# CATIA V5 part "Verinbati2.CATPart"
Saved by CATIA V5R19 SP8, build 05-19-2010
Part number: Vérin bati
Bounding box of the stored display mesh (mm): x -45 to 45, y -60 to 190, z -45 to 45
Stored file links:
  C:\Users\ThinkMotion\Desktop\EU_thinkMotion\iao\IAO_MMS_Groupe3\yschmidt\Train1434_yschmidt\Train1434_yschmidt\Verinbati2.CATPart
  C:\Users\ThinkMotion\Desktop\EU_thinkMotion\iao\IAO_MMS_Groupe3\yschmidt\Train1434_yschmidt\Train1434_yschmidt\AssemblageTrainOptimise.CATProduct
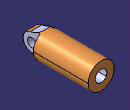
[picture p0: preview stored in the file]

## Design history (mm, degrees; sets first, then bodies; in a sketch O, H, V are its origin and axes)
Set1
  Plane1: linked copy from another document
  Line1: linked copy from another document
Body1 (main body)
  Sketch1 on zx-plane, origin (0, 0, 0), H (-1, 0, 0), V (0, 0, 1)
    circle A1 centre (0, 0) radius 45
    radius A1 = 45
  Pad1: profile Sketch1, direction (0, 1, 0), up to Plane1
  SolidCombine1: FirstComponentProfile Sketch5, FirstComponentDirection Sketch5, SecondComponentProfile Sketch4, SecondComponentDirection Sketch4
  Sketch2 on face of SolidCombine1 from Sketch4.L1, origin (20, -42.0705, -0.8635), H (0, 1, 0), V (0, 0, 1)
    point P1 (12.0705, 0.8635)
    reference projected point E1 (12.0705, 0.8635) from Line1
    coincidence: E1 P1
  Hole1: placed by Sketch2, at (20, -30, 0) direction (-1, 0, 0), diameter 30, through (limit type 6)
  Sketch3 on end face of Pad1, origin (0, 190, 0), H (1, 0, 0), V (0, 0, -1)
    point P1 (0, 0)
  Hole2: placed by Sketch3, at (0, 190, 0) direction (0, -1, 0), diameter 40, depth 180
  Sketch4 on start face of Pad1, origin (0, 0, 0), H (1, 0, 0), V (0, 0, 1)
    arc A1 centre (0, 0) radius 45 from (20, 40.3113) to (-20, 40.3113) ccw
    point P1 (0, 45)
    line L1 (20, 40.3113) -> (20, -40.3113)
    line L2 (-20, 40.3113) -> (-20, -40.3113)
    point P5 (-20, -40.3113)
    arc A2 centre (0, 0) radius 45 from (-20, -40.3113) to (20, -40.3113) ccw
    reference projected circle E1 centre (0, 0) radius 45 from edge [start face of Pad1 | face of Pad1 from Sketch1.A1]
    distance L1 V = 20
    distance L2 V = 20
    coincidence: A1 P1, P1 V, P5 A1, A1 A2, A1 E1
    vertical: L1 V, L2 V
  Sketch5 on yz-plane, origin (0, 0, 0), H (0, 1, 0), V (0, 0, 1)
    arc A1 centre (-30, 0) radius 30 from (-35.7331, 29.4471) to (-35.7331, -29.4471) ccw
    line L1 (0, 45) -> (0, 45)
    point P2 (0, 45)
    axis line L2 (23.5557, 0) -> (-180.0879, 0)
    point P3 (23.5557, 0)
    point P5 (0, -45)
    line L3 (0, 45) -> (0, -45)
    arc A2 centre (-52.9325, 117.7884) radius 90 from (-35.7331, 29.4471) to (0, 45) ccw
    point P6 (-35.7331, 29.4471)
    point P7 (0, 45)
    point P9 (0, -45)
    point P10 (-35.7331, -29.4471)
    arc A3 centre (-52.9325, -117.7884) radius 90 from (-35.7331, -29.4471) to (0, -45) cw
    reference projected point E1 (-30, 0) from Line1
    distance P2 O = 45
    radius A1 = 30
    radius A2 = 90
    coincidence: P2 V, P3 H, P9 P5
    horizontal: L2 H
    symmetry: P2 P5 L2, P7 P9 L2, P6 P10 L2, A2 A3 L2
    vertical: L3 V
    tangency: A2 A1, A2 L1
    concentricity: E1 A1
